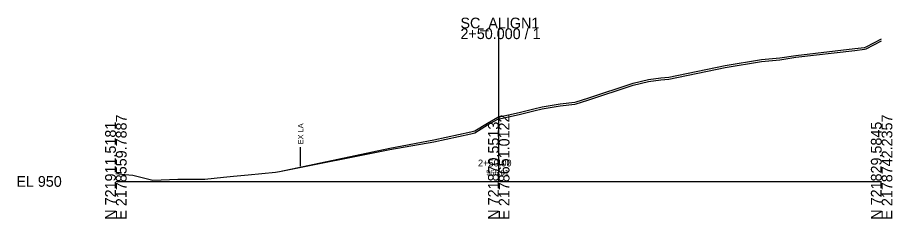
# Model space of a CAD drawing. Extents: x -2342 to 14913, y -10 to 5257.
# Drawn here: x 974.3 to 1202.8, y -9.7 to 42.8 of the extents above; entities that cross this region are included whole.
import ezdxf

# ---------------------------------------------------------------- set-up
doc = ezdxf.new("R2010")
doc.units = 0
for name, color, linetype in [('Default', 7, 'Continuous'), ('GK_Cells', 7, 'Continuous'), ('RW_X_Esmt_LA', 7, 'Continuous'), ('SC_Scratch1', 7, 'Continuous'), ('XS_P_Annotation', 7, 'Continuous'), ('XS_X_Ground_Line', 7, 'Continuous')]:
    doc.layers.add(name, color=color, linetype=linetype)

msp = doc.modelspace()

# ---------------------------------------------------------------- linework, layer by layer
at = {"layer": 'GK_Cells'}
for p, q in [((1100, 0), (1100, 40)), ((1000, 0), (1100, 0)), ((1100, 0), (1200, 0))]:
    msp.add_line(p, q, dxfattribs=at)
at = {"layer": 'RW_X_Esmt_LA'}
msp.add_line((1048.26, 3.99), (1048.26, 8.99), dxfattribs=at)
at = {"layer": 'SC_Scratch1'}
msp.add_lwpolyline([(1000, 2.08), (1002.33, 1.8), (1004.47, 1.6), (1009.65, 0.35), (1016.2, 0.55), (1016.71, 0.59), (1017.54, 0.61), (1023.23, 0.62), (1028.07, 1.11), (1030.72, 1.37), (1034.54, 1.74), (1041.68, 2.43), (1042.72, 2.55), (1071.57, 8.32), (1083.02, 10.35), (1092.73, 12.41), (1093.75, 12.69), (1097.05, 14.75), (1099.77, 16.25), (1105.35, 17.5), (1109.2, 18.46), (1111.3, 18.95), (1116.07, 19.73), (1119.86, 20.19), (1120.22, 20.26), (1123.25, 21.27), (1135.12, 25.13), (1139.07, 26.1), (1142.31, 26.58), (1144.39, 26.7), (1159.17, 29.77), (1168.62, 31.34), (1173.37, 31.79), (1177.58, 32.43), (1192.99, 34.24), (1195.55, 34.53), (1195.95, 34.68), (1200, 36.75)], dxfattribs=at)
at = {"layer": 'XS_X_Ground_Line'}
msp.add_lwpolyline([(1000, 2.08), (1002.33, 1.8), (1004.47, 1.6), (1009.65, 0.35), (1016.2, 0.55), (1016.71, 0.59), (1017.54, 0.61), (1023.23, 0.62), (1028.07, 1.11), (1030.72, 1.37), (1034.54, 1.74), (1041.68, 2.43), (1042.72, 2.55), (1071.57, 8.73), (1083.02, 10.86), (1092.73, 12.92), (1093.75, 13.2), (1097.05, 15.26), (1099.77, 16.76), (1105.35, 18.01), (1109.2, 18.97), (1111.3, 19.46), (1116.07, 20.24), (1119.86, 20.7), (1120.22, 20.77), (1123.25, 21.78), (1135.12, 25.64), (1139.07, 26.61), (1142.31, 27.09), (1144.39, 27.21), (1159.17, 30.28), (1168.62, 31.85), (1173.37, 32.3), (1177.58, 32.94), (1192.99, 34.75), (1195.55, 35.04), (1195.95, 35.19), (1200, 37.26)], dxfattribs=at)

# ---------------------------------------------------------------- texts
at = {"layer": 'Default'}
msp.add_text('-', height=0.0001, dxfattribs=at).set_placement((1000, 0))
at = {"layer": 'GK_Cells'}
for s, p in [('SC_ALIGN1', (1090, 40)), ('2+50.000 / 1', (1090, 37.2)), ('EL 950', (974, -1.4))]:
    msp.add_text(s, height=2.8, dxfattribs=at).set_placement(p)
for s, p in [('E 2178559.7887', (1002.8, -10)), ('E 2178651.0122', (1102.8, -10)), ('E 2178742.2357', (1202.8, -10)), ('N 721911.5181', (1000, -10)), ('N 721870.5513', (1100, -10)), ('N 721829.5845', (1200, -10))]:
    msp.add_text(s, height=2.8, rotation=90, dxfattribs=at).set_placement(p)
at = {"layer": 'RW_X_Esmt_LA'}
msp.add_text('EX LA', height=1.4, rotation=90, dxfattribs=at).set_placement((1048.96, 9.69))
at = {"layer": 'SC_Scratch1'}
msp.add_text('X', height=0.0001, dxfattribs=at).set_placement((1100, 16.81))
at = {"layer": 'XS_P_Annotation'}
for s, height, p in [('2+50.00', 1.8, (1094.58, 3.91)), ('966.81', 1.4, (1096.71, 1.61))]:
    msp.add_text(s, height=height, dxfattribs=at).set_placement(p)

doc.saveas('drawing.dxf')
